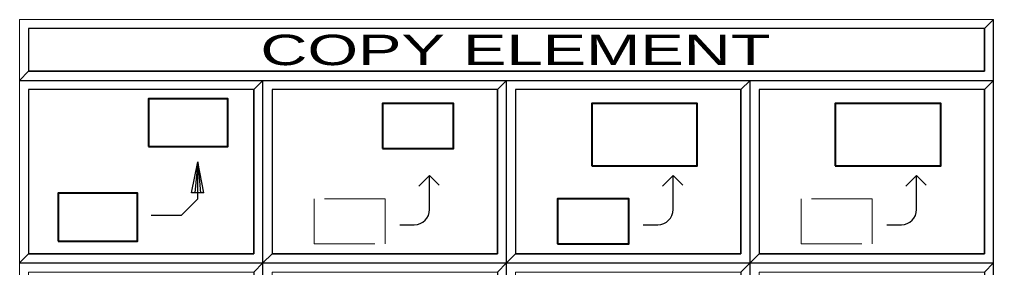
# Model space of a CAD drawing. Extents: x 95906.8 to 95923.6, y 90964.8 to 90972.8.
# Drawn here: x 95912.632 to 95914.232, y 90967.854 to 90968.262 of the extents above; entities that cross this region are included whole.
import ezdxf
from ezdxf.enums import TextEntityAlignment as Align

# ---------------------------------------------------------------- set-up
doc = ezdxf.new("R2010")
doc.units = 0
doc.header["$LTSCALE"] = 0.019
doc.linetypes.add('MEDIUM_DASHED', pattern=[4.5, 3, -1.5])
for name, color, linetype, lineweight in [('11', 7, 'Continuous', 25), ('18', 7, 'Continuous', 25), ('2', 7, 'Continuous', 13), ('3', 7, 'Continuous', 25), ('6', 7, 'Continuous', 25), ('7', 7, 'Continuous', 35)]:
    doc.layers.add(name, color=color, linetype=linetype, lineweight=lineweight)

msp = doc.modelspace()

# ---------------------------------------------------------------- linework, layer by layer
at = {"layer": '11'}
for points in [[(95912.6473, 90967.8767), (95913.0173, 90967.8767), (95913.0173, 90968.1467), (95912.6473, 90968.1467)], [(95913.0473, 90967.8767), (95913.4173, 90967.8767), (95913.4173, 90968.1467), (95913.0473, 90968.1467)], [(95913.4473, 90967.8767), (95913.8173, 90967.8767), (95913.8173, 90968.1467), (95913.4473, 90968.1467)], [(95913.8473, 90967.8767), (95914.2173, 90967.8767), (95914.2173, 90968.1467), (95913.8473, 90968.1467)]]:
    msp.add_lwpolyline(points, close=True, dxfattribs=at)
at = {"layer": '18'}
msp.add_lwpolyline([(95912.6473, 90968.1767), (95914.2173, 90968.1767), (95914.2173, 90968.2467), (95912.6473, 90968.2467)], close=True, dxfattribs=at)
at = {"layer": '2'}
for points in [[(95912.6323, 90968.2617), (95912.6323, 90968.1617), (95912.6473, 90968.1767), (95912.6473, 90968.2467), (95914.2173, 90968.2467), (95914.2323, 90968.2617)], [(95912.6323, 90968.1617), (95912.6323, 90967.8617), (95912.6473, 90967.8767), (95912.6473, 90968.1467), (95913.0173, 90968.1467), (95913.0323, 90968.1617)], [(95913.0323, 90968.1617), (95913.0323, 90967.8617), (95913.0473, 90967.8767), (95913.0473, 90968.1467), (95913.4173, 90968.1467), (95913.4323, 90968.1617)], [(95913.4323, 90968.1617), (95913.4323, 90967.8617), (95913.4473, 90967.8767), (95913.4473, 90968.1467), (95913.8173, 90968.1467), (95913.8323, 90968.1617)], [(95913.8323, 90968.1617), (95913.8323, 90967.8617), (95913.8473, 90967.8767), (95913.8473, 90968.1467), (95914.2173, 90968.1467), (95914.2323, 90968.1617)], [(95912.6323, 90967.8617), (95912.6323, 90967.5617), (95912.6473, 90967.5767), (95912.6473, 90967.8467), (95913.0173, 90967.8467), (95913.0323, 90967.8617)], [(95913.0323, 90967.8617), (95913.0323, 90967.5617), (95913.0473, 90967.5767), (95913.0473, 90967.8467), (95913.4173, 90967.8467), (95913.4323, 90967.8617)], [(95913.4323, 90967.8617), (95913.4323, 90967.5617), (95913.4473, 90967.5767), (95913.4473, 90967.8467), (95913.8173, 90967.8467), (95913.8323, 90967.8617)], [(95913.8323, 90967.8617), (95913.8323, 90967.5617), (95913.8473, 90967.5767), (95913.8473, 90967.8467), (95914.2173, 90967.8467), (95914.2323, 90967.8617)]]:
    msp.add_lwpolyline(points, close=True, dxfattribs=at)
at = {"layer": '3'}
for points in [[(95912.6323, 90968.1617), (95914.2323, 90968.1617), (95914.2323, 90968.2617), (95914.2173, 90968.2467), (95914.2173, 90968.1767), (95912.6473, 90968.1767)], [(95912.6323, 90967.8617), (95913.0323, 90967.8617), (95913.0323, 90968.1617), (95913.0173, 90968.1467), (95913.0173, 90967.8767), (95912.6473, 90967.8767)], [(95913.0323, 90967.8617), (95913.4323, 90967.8617), (95913.4323, 90968.1617), (95913.4173, 90968.1467), (95913.4173, 90967.8767), (95913.0473, 90967.8767)], [(95913.4323, 90967.8617), (95913.8323, 90967.8617), (95913.8323, 90968.1617), (95913.8173, 90968.1467), (95913.8173, 90967.8767), (95913.4473, 90967.8767)], [(95913.8323, 90967.8617), (95914.2323, 90967.8617), (95914.2323, 90968.1617), (95914.2173, 90968.1467), (95914.2173, 90967.8767), (95913.8473, 90967.8767)], [(95912.6323, 90967.5617), (95913.0323, 90967.5617), (95913.0323, 90967.8617), (95913.0173, 90967.8467), (95913.0173, 90967.5767), (95912.6473, 90967.5767)], [(95913.0323, 90967.5617), (95913.4323, 90967.5617), (95913.4323, 90967.8617), (95913.4173, 90967.8467), (95913.4173, 90967.5767), (95913.0473, 90967.5767)], [(95913.4323, 90967.5617), (95913.8323, 90967.5617), (95913.8323, 90967.8617), (95913.8173, 90967.8467), (95913.8173, 90967.5767), (95913.4473, 90967.5767)], [(95913.8323, 90967.5617), (95914.2323, 90967.5617), (95914.2323, 90967.8617), (95914.2173, 90967.8467), (95914.2173, 90967.5767), (95913.8473, 90967.5767)]]:
    msp.add_lwpolyline(points, close=True, dxfattribs=at)
at = {"layer": '6'}
for p, q in [((95912.9251, 90967.9769), (95912.9251, 90968.0281)), ((95912.9251, 90968.0281), (95912.9299, 90967.9769)), ((95913.3059, 90968.0052), (95913.2885, 90967.9878)), ((95913.3059, 90968.0052), (95913.3217, 90967.9894)), ((95913.3059, 90967.9495), (95913.3059, 90968.0052)), ((95913.7059, 90968.0052), (95913.6885, 90967.9878)), ((95913.7059, 90968.0052), (95913.7217, 90967.9894)), ((95913.7059, 90967.9495), (95913.7059, 90968.0052)), ((95914.1059, 90968.0052), (95914.0885, 90967.9878)), ((95914.1059, 90968.0052), (95914.1217, 90967.9894)), ((95914.1059, 90967.9495), (95914.1059, 90968.0052)), ((95913.2569, 90967.9245), (95913.2809, 90967.9245)), ((95913.6569, 90967.9245), (95913.6809, 90967.9245)), ((95914.0569, 90967.9245), (95914.0809, 90967.9245))]:
    msp.add_line(p, q, dxfattribs=at)
at = {"layer": '6', "lineweight": 40}
for points in [[(95912.8442, 90968.0528), (95912.9747, 90968.0528), (95912.9747, 90968.1315), (95912.8442, 90968.1315)], [(95913.2284, 90968.0495), (95913.3455, 90968.0495), (95913.3455, 90968.1238), (95913.2284, 90968.1238)], [(95913.5724, 90968.021), (95913.7455, 90968.021), (95913.7455, 90968.1238), (95913.5724, 90968.1238)], [(95913.9724, 90968.021), (95914.1455, 90968.021), (95914.1455, 90968.1238), (95913.9724, 90968.1238)], [(95912.6957, 90967.8977), (95912.8262, 90967.8977), (95912.8262, 90967.9764), (95912.6957, 90967.9764)], [(95913.5161, 90967.8929), (95913.6332, 90967.8929), (95913.6332, 90967.9672), (95913.5161, 90967.9672)]]:
    msp.add_lwpolyline(points, close=True, dxfattribs=at)
at = {"layer": '6'}
for points in [[(95912.8487, 90967.9404), (95912.8982, 90967.9404), (95912.9251, 90967.9673), (95912.9251, 90968.0281)], [(95912.9353, 90967.9769), (95912.9149, 90967.9769), (95912.9251, 90968.0281)], [(95912.9353, 90967.9769), (95912.9251, 90968.0281), (95912.9201, 90967.9769)]]:
    msp.add_lwpolyline(points, dxfattribs=at)
at = {"layer": '6', "linetype": 'MEDIUM_DASHED', "lineweight": 13}
for points in [[(95913.1161, 90967.8929), (95913.2332, 90967.8929), (95913.2332, 90967.9672), (95913.1161, 90967.9672)], [(95913.9161, 90967.8929), (95914.0332, 90967.8929), (95914.0332, 90967.9672), (95913.9161, 90967.9672)]]:
    msp.add_lwpolyline(points, close=True, dxfattribs=at)
at = {"layer": '6'}
for centre in [(95913.2809, 90967.9495), (95913.6809, 90967.9495), (95914.0809, 90967.9495)]:
    msp.add_arc(centre, 0.025, 270, 0, dxfattribs=at)

# ---------------------------------------------------------------- texts
at = {"layer": '7', "width": 1.6}
msp.add_text('      COPY ELEMENT     ', height=0.04999, dxfattribs=at).set_placement((95913.4322, 90968.1867), align=Align.CENTER)

doc.saveas('drawing.dxf')
